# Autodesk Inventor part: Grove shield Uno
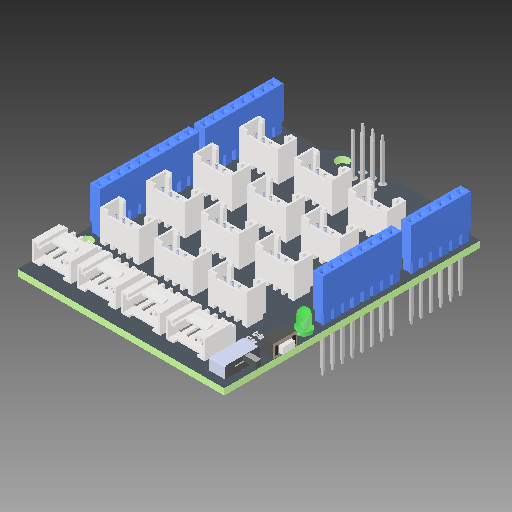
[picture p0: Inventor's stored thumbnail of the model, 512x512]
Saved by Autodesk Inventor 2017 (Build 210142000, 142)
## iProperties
Created: 2017-04
Part Number: Grove shield Uno
Material: Générique
Document SubType Name: Modeling
Designer: ficho
Density: 1 g/cm^3
Appearance: Par défaut
Mass: 11.1121 g
Surface Area: 234.949 cm^2
Volume: 11.1121 cm^3
Sending System: SolidWorks 2012
Last Author: Claude ROBERT
Last Saved: 2017-04-11
Author: ficho
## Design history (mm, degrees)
feature "PCB_uno_shield:1"
feature "broche wrapping 8F:1"
feature "broche wrapping 8F:2"
feature "broche wrapping 8F:3"
feature "broche wrapping 8F:4"
feature "broche wrapping 8F:5"
feature "broche wrapping 8F:6"
feature "broche wrapping 8F:7"
feature "broche wrapping 8F:8"
feature "broche wrapping 8F:9"
feature "broche wrapping 8F:10"
feature "broche wrapping 8F:11"
feature "broche wrapping 8F:12"
feature "broche wrapping 8F:13"
feature "broche wrapping 8F:14"
feature "broche wrapping 8F:15"
feature "broche wrapping 8F:16"
feature "broche wrapping 8F:17"
feature "broche wrapping 8F:18"
feature "spacer 1pt:1"
feature "spacer 1pt:2"
feature "spacer 1pt:3"
feature "spacer 1pt:4"
feature "spacer 2pt  réduit:1"
feature "broche wrapping 2x3F:1"
feature "broche wrapping 2x3F:2"
feature "broche wrapping 2x3F:3"
feature "broche wrapping 2x3F:4"
feature "broche wrapping 2x3F:5"
feature "broche wrapping 2x3F:6"
feature "broche wrapping 2x3F:7"
feature "broche wrapping 10F:1"
feature "broche wrapping 10F:2"
feature "broche wrapping 10F:3"
feature "broche wrapping 10F:4"
feature "broche wrapping 10F:5"
feature "broche wrapping 10F:6"
feature "broche wrapping 10F:7"
feature "broche wrapping 10F:8"
feature "broche wrapping 10F:9"
feature "broche wrapping 10F:10"
feature "broche wrapping 10F:11"
feature "broche wrapping 6F:1"
feature "broche wrapping 6F:2"
feature "broche wrapping 6F:3"
feature "broche wrapping 6F:4"
feature "broche wrapping 6F:5"
feature "broche wrapping 6F:6"
feature "broche wrapping 6F:7"
feature "Connecteur Grove (droit):1"
feature "Connecteur Grove (droit):2"
feature "Connecteur Grove (droit):3"
feature "Connecteur Grove (droit):4"
feature "Connecteur Grove (droit):5"
feature "Connecteur Grove (coudé):1"
feature "spacer 2pt  réduit:2"
feature "spacer 2pt  réduit:3"
feature "Connecteur Grove (droit):6"
feature "Connecteur Grove (droit):7"
feature "Connecteur Grove (droit):8"
feature "Connecteur Grove (droit):9"
feature "Connecteur Grove (droit):10"
feature "Connecteur Grove (droit):11"
feature "Connecteur Grove (droit):12"
feature "Connecteur Grove (droit):13"
feature "Connecteur Grove (droit):14"
feature "Connecteur Grove (droit):15"
feature "Connecteur Grove (droit):16"
feature "Connecteur Grove (droit):17"
feature "Connecteur Grove (droit):18"
feature "Connecteur Grove (droit):19"
feature "Connecteur Grove (droit):20"
feature "Connecteur Grove (droit):21"
feature "Connecteur Grove (droit):22"
feature "Connecteur Grove (droit):23"
feature "Connecteur Grove (droit):24"
feature "Connecteur Grove (droit):25"
feature "Connecteur Grove (droit):26"
feature "Connecteur Grove (droit):27"
feature "Connecteur Grove (droit):28"
feature "Connecteur Grove (droit):29"
feature "Connecteur Grove (droit):30"
feature "Connecteur Grove (droit):31"
feature "Connecteur Grove (droit):32"
feature "Connecteur Grove (droit):33"
feature "Connecteur Grove (droit):34"
feature "Connecteur Grove (droit):35"
feature "Connecteur Grove (droit):36"
feature "Connecteur Grove (droit):37"
feature "Connecteur Grove (droit):38"
feature "Connecteur Grove (droit):39"
feature "Connecteur Grove (droit):40"
feature "Connecteur Grove (droit):41"
feature "Connecteur Grove (droit):42"
feature "Connecteur Grove (droit):43"
feature "Connecteur Grove (droit):44"
feature "Connecteur Grove (droit):45"
feature "Connecteur Grove (droit):46"
feature "Connecteur Grove (droit):47"
feature "Connecteur Grove (droit):48"
feature "Connecteur Grove (droit):49"
feature "Connecteur Grove (droit):50"
feature "Connecteur Grove (droit):51"
feature "Connecteur Grove (droit):52"
feature "Connecteur Grove (droit):53"
feature "Connecteur Grove (droit):54"
feature "Connecteur Grove (droit):55"
feature "Connecteur Grove (droit):56"
feature "Connecteur Grove (droit):57"
feature "Connecteur Grove (droit):58"
feature "Connecteur Grove (droit):59"
feature "Connecteur Grove (droit):60"
feature "Connecteur Grove (coudé):2"
feature "Connecteur Grove (coudé):3"
feature "Connecteur Grove (coudé):4"
feature "spacer 1pt:5"
feature "spacer 1pt:6"
feature "spacer 1pt:7"
feature "spacer 1pt:8"
feature "spacer 1pt:9"
feature "spacer 1pt:10"
feature "spacer 1pt:11"
feature "spacer 1pt:12"
feature "spacer 1pt:13"
feature "spacer 1pt:14"
feature "spacer 1pt:15"
feature "spacer 1pt:16"
feature "spacer 1pt:17"
feature "spacer 1pt:18"
feature "spacer 1pt:19"
feature "spacer 1pt:20"
feature "spacer 1pt:21"
feature "spacer 1pt:22"
feature "spacer 1pt:23"
feature "spacer 1pt:24"
feature "spacer 1pt:25"
feature "spacer 1pt:26"
feature "spacer 1pt:27"
feature "spacer 1pt:28"
feature "spacer 1pt:29"
feature "spacer 1pt:30"
feature "spacer 1pt:31"
feature "spacer 1pt:32"
feature "Bouton_RST:1"
feature "Switch:1"
feature "LED:1"
feature "LED:2"
feature "LED:3"
feature "LED:4"
feature "603 resistor 102:1"
feature "603 resistor 102:2"
feature "603 resistor 102:3"
feature "603 resistor 102:4"
feature "603 resistor 102:5"
feature "603 resistor 102:6"
feature "603 resistor 102:7"
feature "603 resistor 102:8"
node "Solide1"
node "Solide2"
node "Solide3"
node "Solide4"
node "Solide5"
node "Solide6"
node "Solide7"
node "Solide8"
node "Solide9"
node "Solide10"
node "Solide11"
node "Solide12"
node "Solide13"
node "Solide14"
node "Solide15"
node "Solide16"
node "Solide17"
node "Solide18"
node "Solide19"
node "Solide20"
node "Solide21"
node "Solide22"
node "Solide23"
node "Solide24"
node "Solide25"
node "Solide26"
node "Solide27"
node "Solide28"
node "Solide29"
node "Solide30"
node "Solide31"
node "Solide32"
node "Solide33"
node "Solide34"
node "Solide35"
node "Solide36"
node "Solide37"
node "Solide38"
node "Solide39"
node "Solide40"
node "Solide41"
node "Solide42"
node "Solide43"
node "Solide44"
node "Solide45"
node "Solide46"
node "Solide47"
node "Solide48"
node "Solide49"
node "Solide50"
node "Solide51"
node "Solide52"
node "Solide53"
node "Solide54"
node "Solide55"
node "Solide56"
node "Solide57"
node "Solide58"
node "Solide59"
node "Solide60"
node "Solide61"
node "Solide62"
node "Solide63"
node "Solide64"
node "Solide65"
node "Solide66"
node "Solide67"
node "Solide68"
node "Solide69"
node "Solide70"
node "Solide71"
node "Solide72"
node "Solide73"
node "Solide74"
node "Solide75"
node "Solide76"
node "Solide77"
node "Solide78"
node "Solide79"
node "Solide80"
node "Solide81"
node "Solide82"
node "Solide83"
node "Solide84"
node "Solide85"
node "Solide86"
node "Solide87"
node "Solide88"
node "Solide89"
node "Solide90"
node "Solide91"
node "Solide92"
node "Solide93"
node "Solide94"
node "Solide95"
node "Solide96"
node "Solide97"
node "Solide98"
node "Solide99"
node "Solide100"
node "Solide101"
node "Solide102"
node "Solide103"
node "Solide104"
node "Solide105"
node "Solide106"
node "Solide107"
node "Solide108"
node "Solide109"
node "Solide110"
node "Solide111"
node "Solide112"
node "Solide113"
node "Solide114"
node "Solide115"
node "Solide116"
node "Solide117"
node "Solide118"
node "Solide119"
node "Solide120"
node "Solide121"
node "Solide122"
node "Solide123"
node "Solide124"
node "Solide125"
node "Solide126"
node "Solide127"
node "Solide128"
node "Solide129"
node "Solide130"
node "Solide131"
node "Solide132"
node "Solide133"
node "Solide134"
node "Solide135"
node "Solide136"
node "Solide137"
node "Solide138"
node "Solide139"
node "Solide140"
node "Solide141"
node "Solide142"
node "Solide143"
node "Solide144"
node "Solide145"
node "Solide146"
node "Solide147"
node "Solide148"
node "Solide149"
node "Solide150"
node "Solide151"
node "Solide152"
node "Solide153"
node "Solide154"
node "Solide155"
node "Solide156"
node "Solide157"
